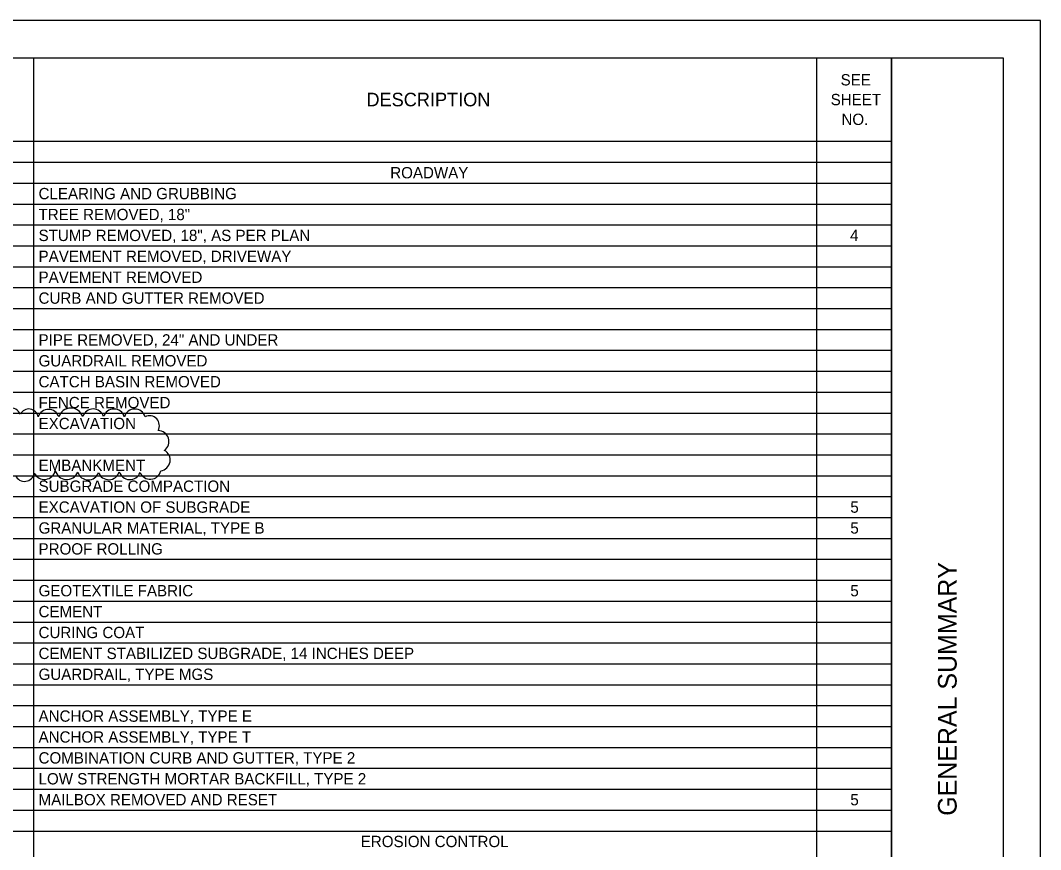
# Model space of a CAD drawing. Extents: x 0 to 36.7, y 0 to 22.
# Drawn here: x 20.33 to 34, y 10.89 to 22 of the extents above; entities that cross this region are included whole.
import ezdxf

# ---------------------------------------------------------------- set-up
doc = ezdxf.new("R2010")
doc.units = 0
for name, color, linetype in [('Default', 7, 'Continuous'), ('SC_Scratch2', 7, 'Continuous'), ('SH_Border', 7, 'Continuous'), ('SH_Cut_Line', 7, 'Continuous'), ('SH_Data', 7, 'Continuous')]:
    doc.layers.add(name, color=color, linetype=linetype)

msp = doc.modelspace()

# ---------------------------------------------------------------- linework, layer by layer
at = {"layer": 'Default'}
for p, q in [((1.5, 21.5), (32, 21.5)), ((20.505, 21.5), (20.505, 0.5)), ((30.995, 21.5), (30.995, 0.5)), ((32, 21.5), (32, 0.5)), ((1.5, 20.38), (32, 20.38)), ((1.5, 20.1), (32, 20.1)), ((1.5, 19.82), (32, 19.82)), ((1.5, 19.54), (32, 19.54)), ((1.5, 19.26), (32, 19.26)), ((1.5, 18.98), (32, 18.98)), ((1.5, 18.7), (32, 18.7)), ((1.5, 18.42), (32, 18.42)), ((1.5, 18.14), (32, 18.14)), ((1.5, 17.86), (32, 17.86)), ((1.5, 17.58), (32, 17.58)), ((1.5, 17.3), (32, 17.3)), ((1.5, 17.02), (32, 17.02)), ((1.5, 16.74), (32, 16.74)), ((1.5, 16.46), (32, 16.46)), ((1.5, 16.18), (32, 16.18)), ((1.5, 15.9), (32, 15.9)), ((1.5, 15.62), (32, 15.62)), ((1.5, 15.34), (32, 15.34)), ((1.5, 15.06), (32, 15.06)), ((1.5, 14.78), (32, 14.78)), ((1.5, 14.5), (32, 14.5)), ((1.5, 14.22), (32, 14.22)), ((1.5, 13.94), (32, 13.94)), ((1.5, 13.66), (32, 13.66)), ((1.5, 13.38), (32, 13.38)), ((1.5, 13.1), (32, 13.1)), ((1.5, 12.82), (32, 12.82)), ((1.5, 12.54), (32, 12.54)), ((1.5, 12.26), (32, 12.26)), ((1.5, 11.98), (32, 11.98)), ((1.5, 11.7), (32, 11.7)), ((1.5, 11.42), (32, 11.42)), ((1.5, 11.14), (32, 11.14))]:
    msp.add_line(p, q, dxfattribs=at)
at = {"layer": 'SC_Scratch2'}
for centre, radius, start, end in [((20.194, 16.661), 0.147, 24.8038, 169.8038), ((20.44, 16.668), 0.126, 8.7979, 153.7979), ((20.704, 16.643), 0.146, 17.5, 162.5), ((21.004, 16.639), 0.168, 18.3245, 163.3245), ((21.303, 16.648), 0.146, 17.5, 162.5), ((21.581, 16.647), 0.146, 17.3666, 162.3666), ((21.86, 16.647), 0.146, 17.5, 162.5), ((22.057, 16.571), 0.133, 330.6644, 115.6644), ((22.173, 16.359), 0.146, 304.9137, 89.9137), ((22.189, 16.11), 0.146, 277.5945, 62.5945), ((20.383, 15.959), 0.135, 204.6591, 349.6591), ((20.649, 15.997), 0.147, 204.9682, 349.9682), ((20.949, 16.007), 0.158, 193.028, 338.028), ((21.235, 15.99), 0.146, 196.9061, 341.9061), ((21.512, 15.993), 0.146, 199.3211, 344.3211), ((21.793, 15.993), 0.146, 195.4005, 340.4005), ((22.066, 15.998), 0.146, 201.9384, 346.9384)]:
    msp.add_arc(centre, radius, start, end, dxfattribs=at)
at = {"layer": 'SH_Border'}
msp.add_line((32, 0.5), (32, 21.5), dxfattribs=at)
msp.add_lwpolyline([(1.5, 21.5), (33.5, 21.5), (33.5, 0.5), (1.5, 0.5)], close=True, dxfattribs=at)
at = {"layer": 'SH_Cut_Line'}
msp.add_lwpolyline([(0, 0), (34, 0), (34, 22), (0, 22)], close=True, dxfattribs=at)

# ---------------------------------------------------------------- texts
at = {"layer": 'Default'}
for s, height, p in [('SEE ', 0.1515, (31.32, 21.129)), ('DESCRIPTION', 0.18184, (24.965, 20.849)), ('SHEET ', 0.1515, (31.187, 20.864)), ('NO.', 0.1515, (31.331, 20.599)), ('ROADWAY', 0.1515, (25.284, 19.884)), ('CLEARING AND GRUBBING', 0.15153, (20.571, 19.604)), ('TREE REMOVED, 18"', 0.15153, (20.571, 19.324)), ('STUMP REMOVED, 18", AS PER PLAN', 0.15153, (20.571, 19.044)), ('4', 0.152, (31.446, 19.044)), ('PAVEMENT REMOVED, DRIVEWAY', 0.15153, (20.571, 18.764)), ('PAVEMENT REMOVED', 0.15153, (20.571, 18.484)), ('CURB AND GUTTER REMOVED', 0.15153, (20.571, 18.204)), ('PIPE REMOVED, 24" AND UNDER', 0.15153, (20.571, 17.644)), ('GUARDRAIL REMOVED', 0.15153, (20.571, 17.364)), ('CATCH BASIN REMOVED', 0.15153, (20.571, 17.084)), ('FENCE REMOVED', 0.15153, (20.571, 16.804)), ('EXCAVATION', 0.1515, (20.571, 16.524)), ('EMBANKMENT', 0.1515, (20.571, 15.964)), ('SUBGRADE COMPACTION', 0.15153, (20.571, 15.684)), ('EXCAVATION OF SUBGRADE', 0.15153, (20.571, 15.404)), ('5', 0.152, (31.45, 15.404)), ('GRANULAR MATERIAL, TYPE B', 0.15153, (20.571, 15.124)), ('5', 0.152, (31.45, 15.124)), ('PROOF ROLLING', 0.15153, (20.571, 14.844)), ('GEOTEXTILE FABRIC', 0.15153, (20.571, 14.284)), ('5', 0.152, (31.45, 14.284)), ('CEMENT', 0.1515, (20.571, 14.004)), ('CURING COAT', 0.15153, (20.571, 13.724)), ('CEMENT STABILIZED SUBGRADE, 14 INCHES DEEP', 0.15153, (20.571, 13.444)), ('GUARDRAIL, TYPE MGS', 0.15153, (20.571, 13.164)), ('ANCHOR ASSEMBLY, TYPE E', 0.15153, (20.571, 12.604)), ('ANCHOR ASSEMBLY, TYPE T', 0.15153, (20.571, 12.324)), ('COMBINATION CURB AND GUTTER, TYPE 2', 0.15153, (20.571, 12.044)), ('LOW STRENGTH MORTAR BACKFILL, TYPE 2', 0.15153, (20.571, 11.764)), ('MAILBOX REMOVED AND RESET', 0.15153, (20.571, 11.484)), ('5', 0.152, (31.45, 11.484)), ('EROSION CONTROL', 0.15153, (24.889, 10.924))]:
    msp.add_text(s, height=height, dxfattribs=at).set_placement(p)
at = {"layer": 'SH_Data'}
msp.add_text('GENERAL SUMMARY', height=0.25, rotation=90, dxfattribs=at).set_placement((32.875, 11.344))

doc.saveas('drawing.dxf')
